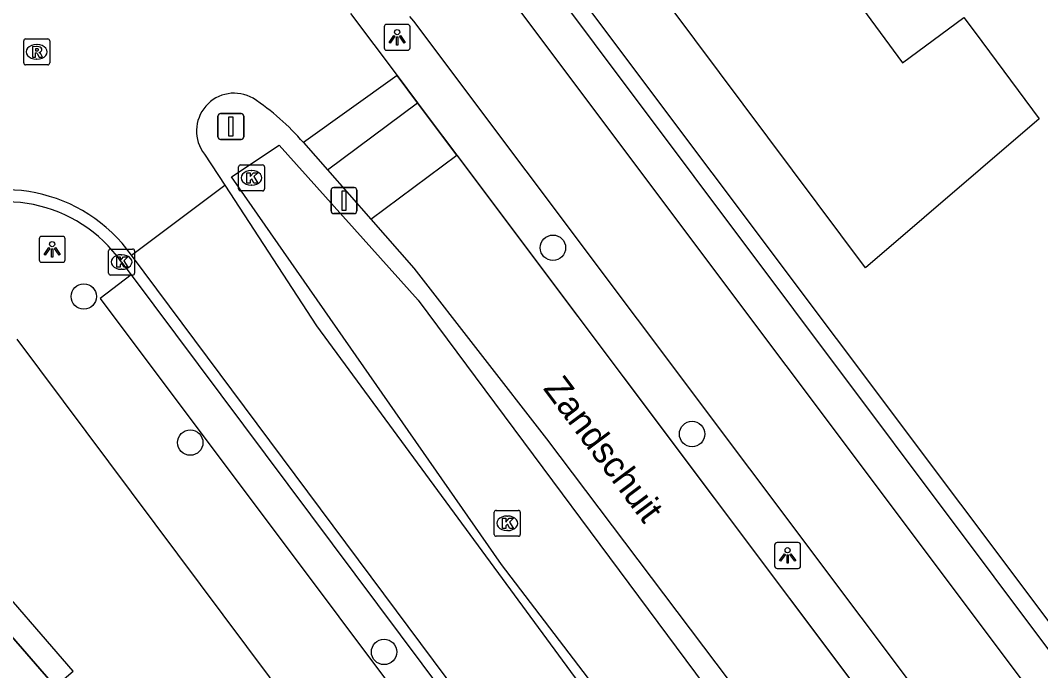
# Model space of a CAD drawing. Extents: x 155888 to 156864, y 383882 to 384671.
# Drawn here: x 156776.8 to 156816.08, y 384340.93 to 384365.97 of the extents above; entities that cross this region are included whole.
import ezdxf

# ---------------------------------------------------------------- set-up
doc = ezdxf.new("R2010")
doc.units = 0
for name, color, linetype in [('IMGEO_Afsluitpaal', 7, 'Continuous'), ('IMGEO_Boom', 7, 'Continuous'), ('IMGEO_Fietspad_gesloten', 7, 'Continuous'), ('IMGEO_Greppel_droge_sloot', 7, 'Continuous'), ('IMGEO_Haag', 7, 'Continuous'), ('IMGEO_Kolk', 7, 'Continuous'), ('IMGEO_Lichtpunt', 7, 'Continuous'), ('IMGEO_Openbare_ruimte_label', 7, 'Continuous'), ('IMGEO_Pand', 7, 'Continuous'), ('IMGEO_Pand_overbouw', 7, 'Continuous'), ('IMGEO_Rijbaan_lokaal_gesloten', 7, 'Continuous'), ('IMGEO_Rijbaan_lokaal_open', 7, 'Continuous'), ('IMGEO_Rioolput', 7, 'Continuous'), ('IMGEO_Verkeersbordpaal', 7, 'Continuous'), ('IMGEO_Voetpad_open', 7, 'Continuous')]:
    doc.layers.add(name, color=color, linetype=linetype)

msp = doc.modelspace()

# ---------------------------------------------------------------- linework, layer by layer
at = {"layer": 'IMGEO_Afsluitpaal'}
for p, q in [((156788.866, 384359.53), (156789.656, 384359.53)), ((156789.656, 384359.53), (156788.866, 384359.53)), ((156788.766, 384358.63), (156788.766, 384359.43)), ((156788.766, 384359.43), (156788.766, 384358.63)), ((156789.756, 384359.43), (156789.756, 384358.63)), ((156789.756, 384358.63), (156789.756, 384359.43)), ((156789.656, 384358.53), (156788.866, 384358.53)), ((156788.866, 384358.53), (156789.656, 384358.53))]:
    msp.add_line(p, q, dxfattribs=at)
msp.add_lwpolyline([(156789.186, 384359.405), (156789.336, 384359.405), (156789.336, 384358.655), (156789.186, 384358.655), (156789.186, 384359.405)], dxfattribs=at)
for centre, start, end in [((156788.866, 384359.43), 90, 180), ((156788.866, 384359.43), 90, 180), ((156789.656, 384359.43), 0, 90), ((156789.656, 384359.43), 360, 90), ((156788.866, 384358.63), 180, 270), ((156788.866, 384358.63), 180, 270), ((156789.656, 384358.63), 270, 0), ((156789.656, 384358.63), 270, 0)]:
    msp.add_arc(centre, 0.1, start, end, dxfattribs=at)
at = {"layer": 'IMGEO_Boom'}
for centre in [(156797.306, 384357.215), (156779.244, 384355.337), (156802.661, 384350.042), (156783.342, 384349.711), (156790.805, 384341.651)]:
    msp.add_circle(centre, 0.489, dxfattribs=at)
at = {"layer": 'IMGEO_Fietspad_gesloten'}
for points in [[(156829.644, 384321.55), (156794.611, 384368.257), (156790.032, 384374.386)], [(156791.786, 384366.121), (156791.933, 384365.945), (156822.101, 384325.753)], [(156780.698, 384356.664), (156781.068, 384356.17)], [(156781.068, 384356.17), (156808.643, 384319.266)]]:
    msp.add_lwpolyline(points, dxfattribs=at)
msp.add_arc((156776.202, 384353.475), 5.512, 35.3469, 121.481, dxfattribs=at)
at = {"layer": 'IMGEO_Greppel_droge_sloot'}
msp.add_lwpolyline([(156813.111, 384321.708), (156795.329, 384345.015), (156784.931, 384359.95), (156786.768, 384361.16), (156792.123, 384355.202), (156815.709, 384323.468), (156813.111, 384321.708)], dxfattribs=at)
at = {"layer": 'IMGEO_Haag'}
for points in [[(156791.656, 384375.785), (156798.64, 384366.477), (156817.787, 384340.957)], [(156791.305, 384363.846), (156792.096, 384362.792)], [(156792.096, 384362.792), (156793.053, 384361.516)], [(156793.053, 384361.516), (156819.178, 384326.696)]]:
    msp.add_lwpolyline(points, dxfattribs=at)
at = {"layer": 'IMGEO_Kolk'}
for p, q in [((156785.201, 384359.479), (156785.201, 384360.331)), ((156785.276, 384360.405), (156786.128, 384360.405)), ((156786.202, 384360.331), (156786.202, 384359.479)), ((156785.689, 384360.185), (156785.714, 384360.185)), ((156785.712, 384359.625), (156785.687, 384359.625)), ((156786.128, 384359.405), (156785.276, 384359.405)), ((156780.198, 384356.239), (156780.198, 384357.091)), ((156780.273, 384357.165), (156781.125, 384357.165)), ((156781.199, 384357.091), (156781.199, 384356.239)), ((156780.686, 384356.945), (156780.711, 384356.945)), ((156780.709, 384356.385), (156780.684, 384356.385)), ((156781.125, 384356.165), (156780.273, 384356.165)), ((156795.047, 384346.178), (156795.047, 384347.03)), ((156795.122, 384347.104), (156795.974, 384347.104)), ((156795.535, 384346.884), (156795.56, 384346.884)), ((156796.048, 384347.03), (156796.048, 384346.178)), ((156795.974, 384346.104), (156795.122, 384346.104)), ((156795.558, 384346.324), (156795.533, 384346.324))]:
    msp.add_line(p, q, dxfattribs=at)
for points in [[(156785.201, 384359.479), (156785.201, 384360.331)], [(156785.276, 384360.405), (156786.128, 384360.405)], [(156786.202, 384360.331), (156786.202, 384359.479)], [(156785.522, 384360.105), (156785.645, 384360.105), (156785.645, 384359.954), (156785.775, 384360.105), (156785.939, 384360.105), (156785.793, 384359.954), (156785.946, 384359.705), (156785.794, 384359.705), (156785.709, 384359.869), (156785.645, 384359.802), (156785.645, 384359.705), (156785.522, 384359.705), (156785.522, 384360.105)], [(156786.128, 384359.405), (156785.276, 384359.405)], [(156780.198, 384356.239), (156780.198, 384357.091)], [(156780.273, 384357.165), (156781.125, 384357.165)], [(156781.199, 384357.091), (156781.199, 384356.239)], [(156780.519, 384356.865), (156780.642, 384356.865), (156780.642, 384356.714), (156780.772, 384356.865), (156780.936, 384356.865), (156780.79, 384356.714), (156780.943, 384356.465), (156780.791, 384356.465), (156780.706, 384356.629), (156780.642, 384356.562), (156780.642, 384356.465), (156780.519, 384356.465), (156780.519, 384356.865)], [(156781.125, 384356.165), (156780.273, 384356.165)], [(156795.047, 384346.178), (156795.047, 384347.03)], [(156795.122, 384347.104), (156795.974, 384347.104)], [(156796.048, 384347.03), (156796.048, 384346.178)], [(156795.368, 384346.804), (156795.491, 384346.804), (156795.491, 384346.653), (156795.621, 384346.804), (156795.785, 384346.804), (156795.639, 384346.653), (156795.792, 384346.404), (156795.64, 384346.404), (156795.555, 384346.568), (156795.491, 384346.501), (156795.491, 384346.404), (156795.368, 384346.404), (156795.368, 384346.804)], [(156795.974, 384346.104), (156795.122, 384346.104)]]:
    msp.add_lwpolyline(points, dxfattribs=at)
for centre, start, end in [((156785.278, 384360.329), 91.552, 178.448), ((156785.278, 384360.329), 91.552, 178.448), ((156786.126, 384360.329), 1.552, 88.448), ((156786.126, 384360.329), 1.552, 88.448), ((156785.278, 384359.481), 181.552, 268.448), ((156785.278, 384359.481), 181.552, 268.448), ((156786.126, 384359.481), 271.552, 358.448), ((156786.126, 384359.481), 271.552, 358.448), ((156780.275, 384357.089), 91.552, 178.448), ((156780.275, 384357.089), 91.552, 178.448), ((156781.123, 384357.089), 1.552, 88.448), ((156781.123, 384357.089), 1.552, 88.448), ((156780.275, 384356.241), 181.552, 268.448), ((156780.275, 384356.241), 181.552, 268.448), ((156781.123, 384356.241), 271.552, 358.448), ((156781.123, 384356.241), 271.552, 358.448), ((156795.124, 384347.028), 91.552, 178.448), ((156795.124, 384347.028), 91.552, 178.448), ((156795.972, 384347.028), 1.552, 88.448), ((156795.972, 384347.028), 1.552, 88.448), ((156795.124, 384346.18), 181.552, 268.448), ((156795.124, 384346.18), 181.552, 268.448), ((156795.972, 384346.18), 271.552, 358.448), ((156795.972, 384346.18), 271.552, 358.448)]:
    msp.add_arc(centre, 0.0765, start, end, dxfattribs=at)
for centre, major_axis, ratio, start_param, end_param in [((156785.688, 384359.905), (-0.387, 0.002), 0.722429, 4.712389, 7.853982), ((156785.713, 384359.905), (-0.39, 0.002), 0.717154, 1.570796, 4.712389), ((156780.685, 384356.665), (-0.387, 0.002), 0.722429, 4.712389, 7.853982), ((156780.71, 384356.665), (-0.39, 0.002), 0.717154, 1.570796, 4.712389), ((156795.534, 384346.604), (-0.387, 0.002), 0.722429, 4.712389, 7.853982), ((156795.559, 384346.604), (-0.39, 0.002), 0.717154, 1.570796, 4.712389)]:
    msp.add_ellipse(centre, major_axis=major_axis, ratio=ratio, start_param=start_param, end_param=end_param, dxfattribs=at)
at = {"layer": 'IMGEO_Lichtpunt'}
for p, q in [((156790.808, 384365.72), (156790.808, 384364.913)), ((156790.808, 384365.72), (156790.808, 384364.913)), ((156791.71, 384365.815), (156790.902, 384365.815)), ((156791.71, 384365.815), (156790.902, 384365.815)), ((156791.804, 384364.913), (156791.804, 384365.72)), ((156791.804, 384364.913), (156791.804, 384365.72)), ((156790.902, 384364.819), (156791.71, 384364.819)), ((156790.902, 384364.819), (156791.71, 384364.819)), ((156777.526, 384357.555), (156777.526, 384356.748)), ((156777.526, 384357.555), (156777.526, 384356.748)), ((156778.428, 384357.65), (156777.62, 384357.65)), ((156778.428, 384357.65), (156777.62, 384357.65)), ((156778.522, 384356.748), (156778.522, 384357.555)), ((156778.522, 384356.748), (156778.522, 384357.555)), ((156777.62, 384356.654), (156778.428, 384356.654)), ((156777.62, 384356.654), (156778.428, 384356.654)), ((156805.841, 384345.77), (156805.841, 384344.963)), ((156805.841, 384345.77), (156805.841, 384344.963)), ((156806.743, 384345.865), (156805.935, 384345.865)), ((156806.743, 384345.865), (156805.935, 384345.865)), ((156806.837, 384344.963), (156806.837, 384345.77)), ((156806.837, 384344.963), (156806.837, 384345.77)), ((156805.935, 384344.869), (156806.743, 384344.869)), ((156805.935, 384344.869), (156806.743, 384344.869))]:
    msp.add_line(p, q, dxfattribs=at)
for points in [[(156791.182, 384365.384), (156791.221, 384365.356), (156791.033, 384365.094), (156790.995, 384365.121), (156791.182, 384365.384)], [(156791.284, 384365.336), (156791.331, 384365.336), (156791.331, 384365.014), (156791.284, 384365.014), (156791.284, 384365.336)], [(156791.394, 384365.356), (156791.432, 384365.383), (156791.619, 384365.121), (156791.58, 384365.093), (156791.394, 384365.356)], [(156777.9, 384357.219), (156777.939, 384357.191), (156777.751, 384356.929), (156777.713, 384356.956), (156777.9, 384357.219)], [(156778.002, 384357.171), (156778.049, 384357.171), (156778.049, 384356.849), (156778.002, 384356.849), (156778.002, 384357.171)], [(156778.112, 384357.191), (156778.15, 384357.218), (156778.337, 384356.956), (156778.298, 384356.928), (156778.112, 384357.191)], [(156806.215, 384345.434), (156806.254, 384345.406), (156806.066, 384345.144), (156806.028, 384345.171), (156806.215, 384345.434)], [(156806.317, 384345.386), (156806.364, 384345.386), (156806.364, 384345.064), (156806.317, 384345.064), (156806.317, 384345.386)], [(156806.427, 384345.406), (156806.465, 384345.433), (156806.652, 384345.171), (156806.613, 384345.143), (156806.427, 384345.406)]]:
    msp.add_lwpolyline(points, dxfattribs=at)
for centre in [(156791.307, 384365.518), (156778.025, 384357.353), (156806.34, 384345.568)]:
    msp.add_circle(centre, 0.0994, dxfattribs=at)
for centre, start, end in [((156790.902, 384365.72), 90, 180), ((156790.902, 384365.72), 90, 180), ((156791.71, 384365.72), 0, 90), ((156791.71, 384365.72), 0, 90), ((156790.902, 384364.913), 180, 270), ((156790.902, 384364.913), 180, 270), ((156791.71, 384364.913), 270, 0), ((156791.71, 384364.913), 270, 360), ((156777.62, 384357.555), 90, 180), ((156777.62, 384357.555), 90, 180), ((156778.428, 384357.555), 0, 90), ((156778.428, 384357.555), 0, 90), ((156777.62, 384356.748), 180, 270), ((156777.62, 384356.748), 180, 270), ((156778.428, 384356.748), 270, 0), ((156778.428, 384356.748), 270, 360), ((156805.935, 384345.77), 90, 180), ((156805.935, 384345.77), 90, 180), ((156806.743, 384345.77), 0, 90), ((156806.743, 384345.77), 0, 90), ((156805.935, 384344.963), 180, 270), ((156805.935, 384344.963), 180, 270), ((156806.743, 384344.963), 270, 0), ((156806.743, 384344.963), 270, 360)]:
    msp.add_arc(centre, 0.0946, start, end, dxfattribs=at)
at = {"layer": 'IMGEO_Pand'}
for points in [[(156807.5, 384368.774), (156810.765, 384364.334), (156813.127, 384366.085), (156813.563, 384365.496), (156816.021, 384362.182), (156809.34, 384356.444), (156796.193, 384374.035)], [(156778.146, 384340.317), (156774.603, 384344.394)]]:
    msp.add_lwpolyline(points, dxfattribs=at)
at = {"layer": 'IMGEO_Pand_overbouw'}
msp.add_lwpolyline([(156774.603, 384344.394), (156778.146, 384340.317), (156778.831, 384340.91), (156775.287, 384344.988)], close=True, dxfattribs=at)
at = {"layer": 'IMGEO_Rijbaan_lokaal_gesloten'}
for points in [[(156789.514, 384366.233), (156791.305, 384363.846)], [(156791.305, 384363.846), (156787.697, 384361.267)], [(156792.096, 384362.792), (156791.305, 384363.846)], [(156787.697, 384361.267), (156788.621, 384360.216)], [(156783.89, 384360.819), (156784.668, 384359.627)], [(156793.606, 384360.779), (156819.178, 384326.696)], [(156781.078, 384356.923), (156784.668, 384359.627)], [(156784.668, 384359.627), (156788.208, 384354.205), (156812.284, 384321.442)], [(156790.29, 384358.319), (156791.949, 384356.433), (156797.059, 384349.852), (156816.139, 384324.569)], [(156809.214, 384319.176), (156781.078, 384356.923)]]:
    msp.add_lwpolyline(points, dxfattribs=at)
for centre, radius, start, end in [((156785.036, 384361.712), 1.453, 59.9422, 217.9052), ((156780.547, 384355.095), 9.446, 40.8005, 56.4719), ((156776.207, 384353.484), 5.963, 35.224, 121.8292)]:
    msp.add_arc(centre, radius, start, end, dxfattribs=at)
at = {"layer": 'IMGEO_Rijbaan_lokaal_open'}
for points in [[(156788.621, 384360.216), (156792.096, 384362.792)], [(156793.053, 384361.516), (156792.096, 384362.792)], [(156792.096, 384362.792), (156792.096, 384362.792)], [(156793.606, 384360.779), (156793.053, 384361.516)], [(156790.29, 384358.319), (156793.606, 384360.779)], [(156788.621, 384360.216), (156790.29, 384358.319)]]:
    msp.add_lwpolyline(points, dxfattribs=at)
at = {"layer": 'IMGEO_Rioolput'}
for p, q in [((156776.93, 384364.331), (156776.93, 384365.183)), ((156777.005, 384365.257), (156777.857, 384365.257)), ((156777.418, 384365.037), (156777.443, 384365.037)), ((156777.931, 384365.183), (156777.931, 384364.331)), ((156777.857, 384364.257), (156777.005, 384364.257)), ((156777.441, 384364.477), (156777.416, 384364.477))]:
    msp.add_line(p, q, dxfattribs=at)
for points in [[(156776.93, 384364.331), (156776.93, 384365.183)], [(156777.005, 384365.257), (156777.857, 384365.257)], [(156777.519, 384364.955), (156777.267, 384364.957), (156777.267, 384364.557)], [(156777.931, 384365.183), (156777.931, 384364.331)], [(156777.267, 384364.557), (156777.391, 384364.557), (156777.391, 384364.719), (156777.402, 384364.719)], [(156777.445, 384364.876), (156777.391, 384364.876), (156777.391, 384364.795)], [(156777.391, 384364.795), (156777.443, 384364.795)], [(156777.449, 384364.69), (156777.52, 384364.557), (156777.66, 384364.557), (156777.595, 384364.683)], [(156777.857, 384364.257), (156777.005, 384364.257)]]:
    msp.add_lwpolyline(points, dxfattribs=at)
for centre, radius, start, end in [((156777.007, 384365.181), 0.0765, 91.552, 178.448), ((156777.007, 384365.181), 0.0765, 91.552, 178.448), ((156777.518, 384364.845), 0.109, 350.3612, 89.416), ((156777.855, 384365.181), 0.0765, 1.552, 88.448), ((156777.855, 384365.181), 0.0765, 1.552, 88.448), ((156777.401, 384364.666), 0.0533, 26.0293, 88.6989), ((156777.427, 384364.984), 0.19, 274.7715, 282.9687), ((156777.451, 384364.78), 0.0964, 77.0061, 93.1865), ((156777.465, 384364.837), 0.0378, 276.6634, 79.6772), ((156777.516, 384364.845), 0.112, 277.5842, 350.9817), ((156777.5, 384364.63), 0.108, 29.5134, 73.7905), ((156777.007, 384364.333), 0.0765, 181.552, 268.448), ((156777.007, 384364.333), 0.0765, 181.552, 268.448), ((156777.855, 384364.333), 0.0765, 271.552, 358.448), ((156777.855, 384364.333), 0.0765, 271.552, 358.448)]:
    msp.add_arc(centre, radius, start, end, dxfattribs=at)
for centre, major_axis, ratio, start_param, end_param in [((156777.417, 384364.757), (-0.387, 0.002), 0.722429, 4.712389, 7.853982), ((156777.442, 384364.757), (-0.39, 0.002), 0.717154, 1.570796, 4.712389)]:
    msp.add_ellipse(centre, major_axis=major_axis, ratio=ratio, start_param=start_param, end_param=end_param, dxfattribs=at)
at = {"layer": 'IMGEO_Verkeersbordpaal'}
for p, q in [((156784.41, 384361.482), (156784.41, 384362.282)), ((156784.41, 384362.282), (156784.41, 384361.482)), ((156784.51, 384362.382), (156785.3, 384362.382)), ((156785.3, 384362.382), (156784.51, 384362.382)), ((156785.4, 384362.282), (156785.4, 384361.482)), ((156785.4, 384361.482), (156785.4, 384362.282)), ((156785.3, 384361.382), (156784.51, 384361.382)), ((156784.51, 384361.382), (156785.3, 384361.382))]:
    msp.add_line(p, q, dxfattribs=at)
msp.add_lwpolyline([(156784.83, 384362.257), (156784.98, 384362.257), (156784.98, 384361.507), (156784.83, 384361.507), (156784.83, 384362.257)], dxfattribs=at)
for centre, start, end in [((156784.51, 384362.282), 90, 180), ((156784.51, 384362.282), 90, 180), ((156785.3, 384362.282), 0, 90), ((156785.3, 384362.282), 360, 90), ((156784.51, 384361.482), 180, 270), ((156784.51, 384361.482), 180, 270), ((156785.3, 384361.482), 270, 0), ((156785.3, 384361.482), 270, 0)]:
    msp.add_arc(centre, 0.1, start, end, dxfattribs=at)
at = {"layer": 'IMGEO_Voetpad_open'}
for points in [[(156829.676, 384324.008), (156791.188, 384375.382)], [(156781.068, 384356.17), (156779.868, 384355.257), (156807.481, 384318.443)], [(156806.695, 384313.529), (156776.684, 384353.691)]]:
    msp.add_lwpolyline(points, dxfattribs=at)

# ---------------------------------------------------------------- texts
at = {"layer": 'IMGEO_Openbare_ruimte_label'}
msp.add_text('Zandschuit', height=1, rotation=306.7897, dxfattribs=at).set_placement((156796.904, 384351.792))

doc.saveas('drawing.dxf')
